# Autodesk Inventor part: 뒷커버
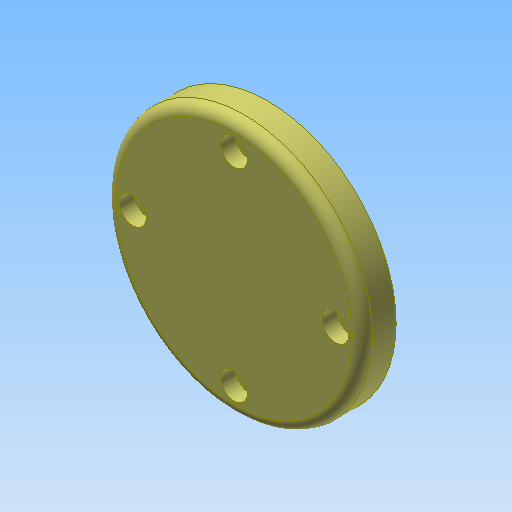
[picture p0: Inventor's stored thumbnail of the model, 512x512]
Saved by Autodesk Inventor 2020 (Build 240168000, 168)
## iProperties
Created: 2010-03
Part Number: 뒷커버
Document SubType Name: Modeling
Designer: 진현석
Density: 1 g/cm^3
Material: 알루미늄 6061
Appearance: 기본값(1)
Author: 진현석
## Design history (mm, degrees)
sketch "스케치1"
  geometry: C1 r 38 at (0, 0); 1 further point
  constraints: 1 centre point, 1 coincident
  dimensions: "d46" = 76 diameter of C1
extrude "돌출1" new body sketch "스케치1" distance "d0" = 10; taper "d1" = 0 deg
sketch "스케치2"
  geometry: C1 r 26 at (0, 0); C2 r 38 at (0, 0) reference
  constraints: 1 centre point, 1 concentric
  dimensions: "d47" = 52 diameter of C1
extrude "돌출3" join sketch "스케치2" distance "d4" = 3; taper "d5" = 0 deg
sketch "스케치4"
  geometry: C1 r 23 at (0, 0); C2 r 26 at (0, 0) reference
  constraints: 1 centre point, 1 concentric
  dimensions: "d40" = 3 radial gap between concentric circles of C2 C1
extrude "돌출5" cut sketch "스케치4" distance "d23" = 6; taper "d24" = 0 deg
fillet "모깎기1" dims "d25" = 3
sketch "스케치5" dims "d41" = 60
  geometry: C1 r 38 at (0, 0) reference; 2 further points
  constraints: 2 vertical alignment, 3 other
hole "구멍2" sketch "스케치5" at (0, 30) diameter "d27" = 4.5; stored, may be unused: countersink angle "d31" = 90 deg, drill point angle "d33" = 118 deg; dims "d28" = 6, "d29" = 8, "d30" = 4.4, "d32" = 8
fillet "모깎기2" dims "d37" = 3
chamfer "모따기1" distance "d43" = 1; stored, may be unused: second distance "d44" = 2, angle "d45" = 45 deg
node "솔리드1"
pattern_circular "원형 패턴2" dims angle "d35" = 360 deg
